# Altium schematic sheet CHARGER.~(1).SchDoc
size A3; SheetNumber: 2; SheetTotal: 2
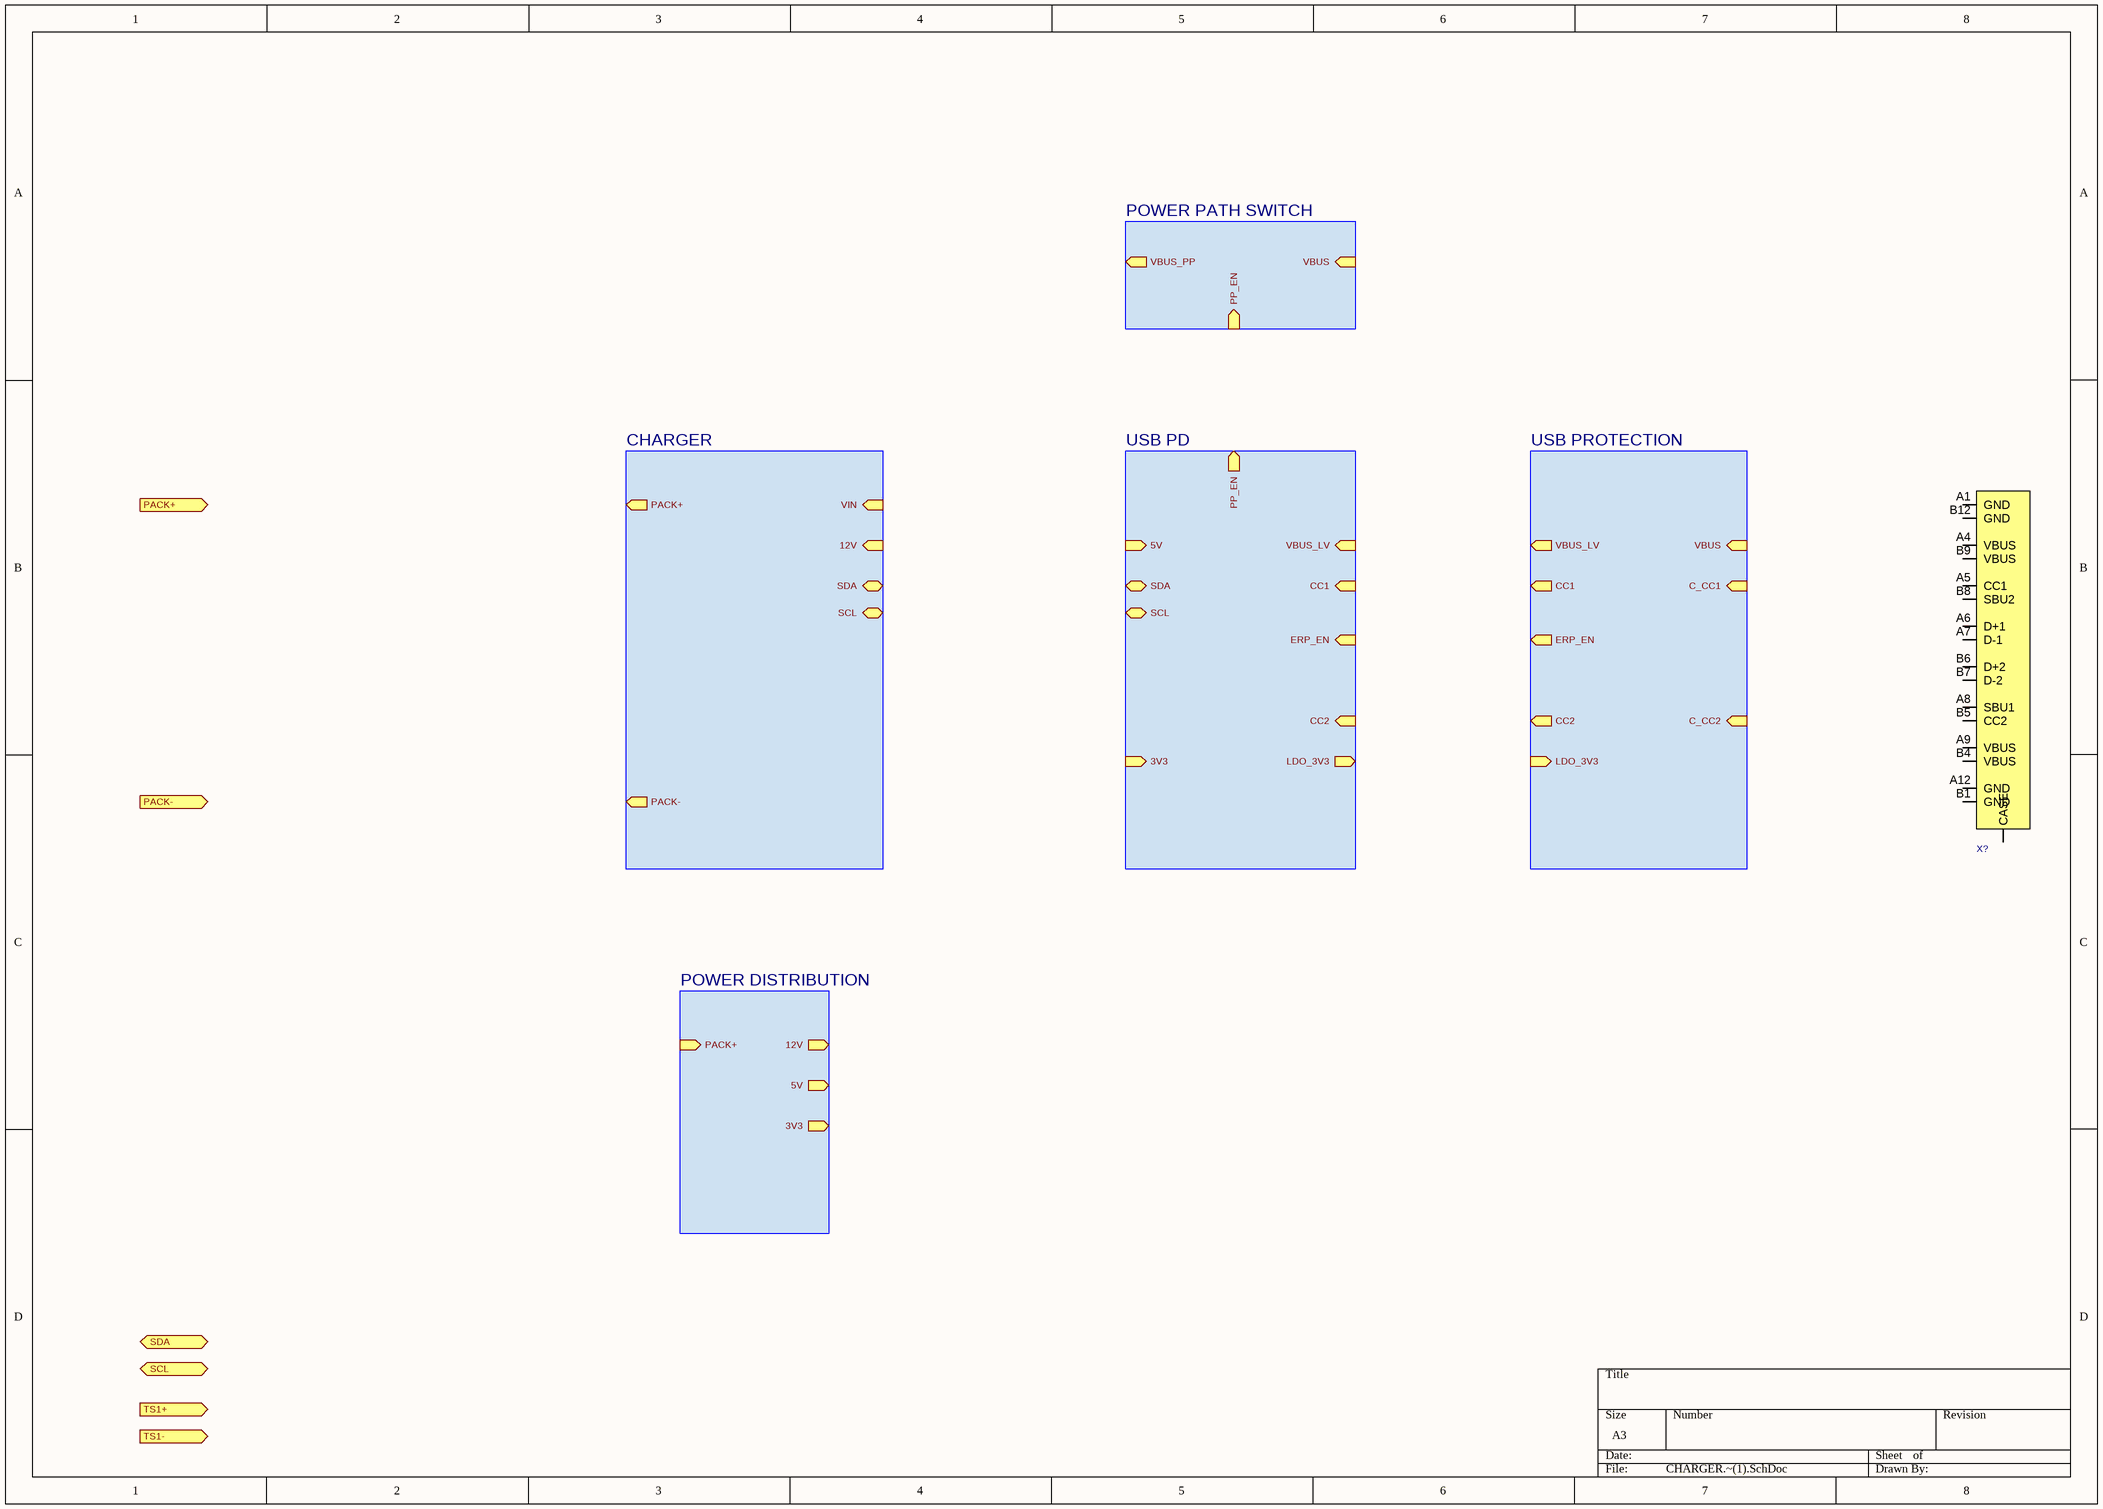
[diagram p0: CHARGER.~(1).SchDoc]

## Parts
X?  TYPE-C 16P LTH6.8  [TYPE-C 16P LTH6.8]  (value not drawn)

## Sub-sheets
CHARGER = Charger.SchDoc: PACK+ (out), VIN (in), SDA (bidir), SCL (bidir), 12V (in), PACK- (out)
POWER DISTRIBUTION = Power distribution.SchDoc: PACK+ (in), 12V (out), 5V (out), 3V3 (out)
POWER PATH SWITCH = Power path switch.SchDoc: VBUS (in), VBUS_PP (out), PP_EN (in)
USB PD = USB PD.SchDoc: VBUS_LV (in), ERP_EN (in), CC1 (in), LDO_3V3 (out), SDA (bidir), SCL (bidir), 5V (in), 3V3 (in), CC2 (in), PP_EN (out)
USB PROTECTION = USB protection.SchDoc: VBUS (in), C_CC1 (in), C_CC2 (in), VBUS_LV (out), ERP_EN (out), CC1 (out), LDO_3V3 (in), CC2 (out)

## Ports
PACK+ (in, see Arhitecture[6C]), PACK- (in, see Arhitecture[6C]), SCL (bidir, see Arhitecture[6C]), SDA (bidir, see Arhitecture[6C]), TS1+ (in, see Arhitecture[6C]), TS1- (in, see Arhitecture[6C])

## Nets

Not connected (* = marked no-connect by the designer): X? A1(GND) A4(VBUS) A5(CC1) A6(D+1) A7(D-1) A8(SBU1) A9(VBUS) A12(GND) B1(GND) B4(VBUS) B5(CC2) B6(D+2) B7(D-2) B8(SBU2) B9(VBUS) B12(GND) CASE

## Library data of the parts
X? = TYPE-C 16P LTH6.8: USB-C 16P SMD Vertical 6.50mmH; Manufacturer: Shou Han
